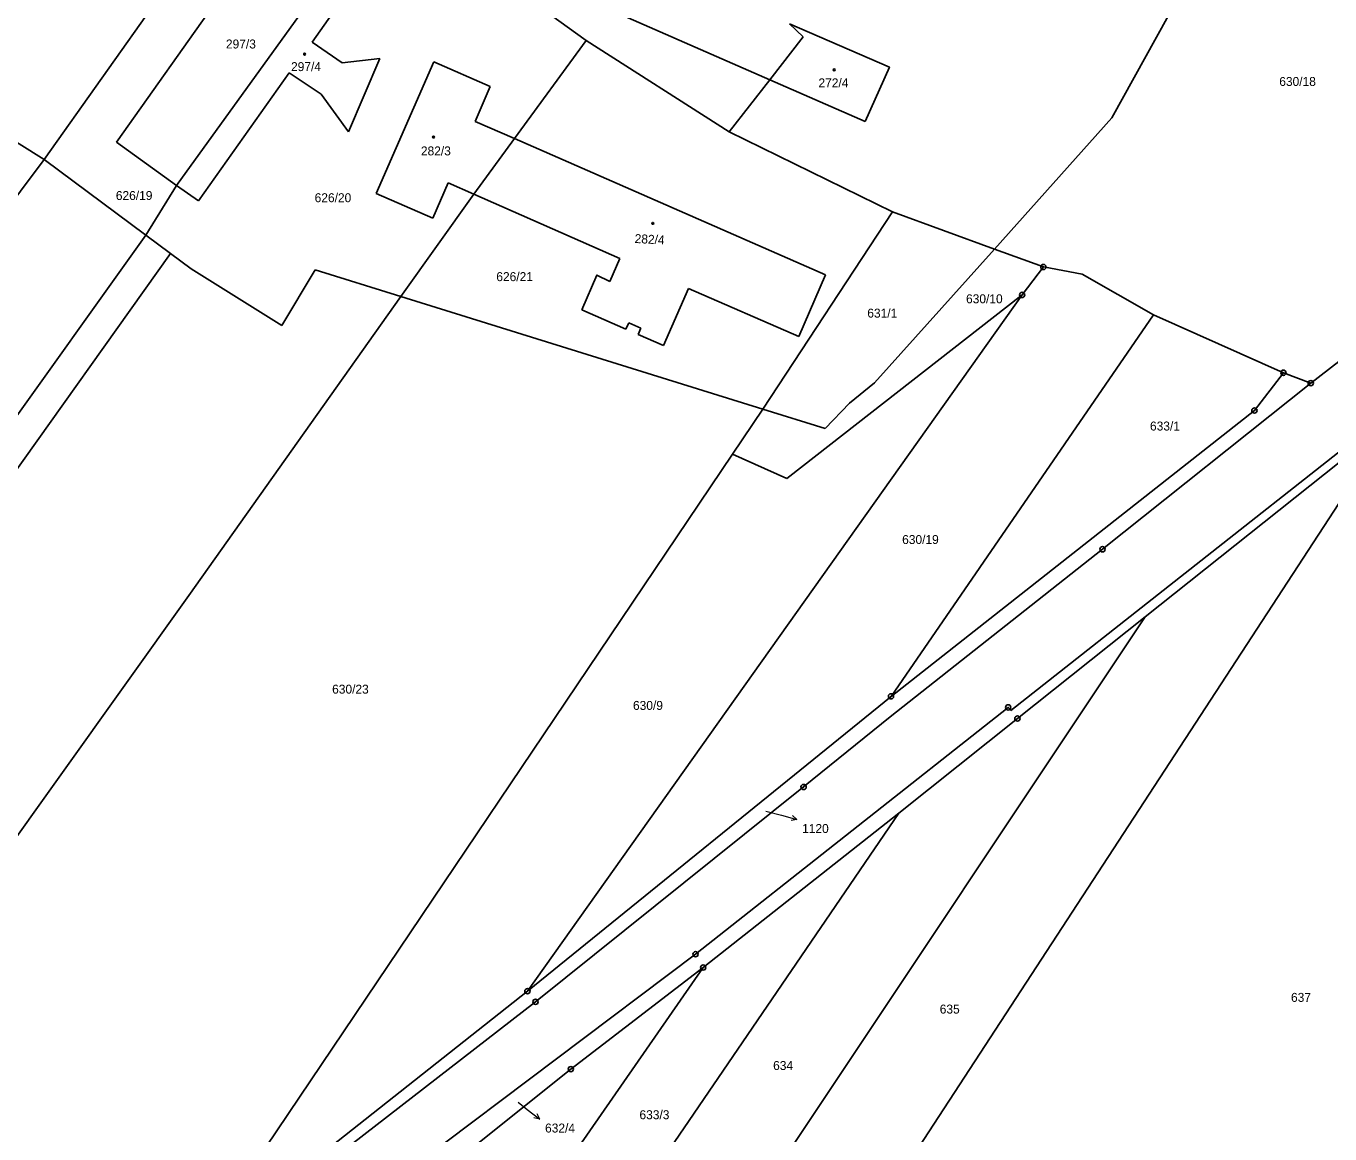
# Model space of a CAD drawing. Extents: x -694609 to -690140, y -1033292 to -1029794.
# Drawn here: x -692351.9 to -692104.2, y -1031915.8 to -1031705.3 of the extents above; entities that cross this region are included whole.
import ezdxf
from ezdxf.enums import TextEntityAlignment as Align

# ---------------------------------------------------------------- set-up
doc = ezdxf.new("R2010")
doc.units = 0
doc.header["$LTSCALE"] = 0.68
for name, color, linetype, lineweight in [('1', 7, 'Continuous', 25), ('5', 7, 'Continuous', 25), ('7', 7, 'Continuous', 13), ('8', 7, 'Continuous', 25)]:
    doc.layers.add(name, color=color, linetype=linetype, lineweight=lineweight)
doc.layers.add('2', color=7, linetype='Continuous')

msp = doc.modelspace()

# ---------------------------------------------------------------- linework, layer by layer
at = {"layer": '1'}
for p, q in [((-692334.77, -1031727.41), (-692299.54, -1031677.74)), ((-692120.78, -1031677.81), (-692145.66, -1031722.81)), ((-692245.5, -1031708.12), (-692283.59, -1031680.54)), ((-692287.71, -1031686.16), (-692323.37, -1031735.66)), ((-692283.83, -1031688.91), (-692297.6, -1031708.4)), ((-692410, -1031692.14), (-692348.49, -1031730.69)), ((-692321.31, -1031692.32), (-692348.49, -1031730.69)), ((-692210.65, -1031715.54), (-692263.5, -1031692.38)), ((-692204.33, -1031707.41), (-692206.91, -1031704.9)), ((-692204.33, -1031707.41), (-692210.65, -1031715.54)), ((-692291.9, -1031712.32), (-692297.6, -1031708.4)), ((-692245.5, -1031708.12), (-692259.11, -1031726.73)), ((-692218.38, -1031725.47), (-692245.5, -1031708.12)), ((-692284.71, -1031711.48), (-692291.9, -1031712.32)), ((-692290.69, -1031725.44), (-692284.71, -1031711.48)), ((-692285.43, -1031737.17), (-692274.48, -1031712.12)), ((-692274.48, -1031712.12), (-692263.73, -1031716.82)), ((-692301.93, -1031714.25), (-692319.15, -1031738.53)), ((-692301.93, -1031714.25), (-692295.83, -1031718.26)), ((-692263.73, -1031716.82), (-692266.63, -1031723.45)), ((-692210.65, -1031715.54), (-692218.38, -1031725.47)), ((-692192.5, -1031723.49), (-692210.65, -1031715.54)), ((-692295.83, -1031718.26), (-692290.69, -1031725.44)), ((-692038.82, -1031719.67), (-692107.88, -1031773.18)), ((-692259.11, -1031726.73), (-692266.63, -1031723.45)), ((-692145.66, -1031722.81), (-692167.96, -1031747.7)), ((-692334.77, -1031727.41), (-692323.37, -1031735.66)), ((-692259.11, -1031726.73), (-692266.83, -1031737.29)), ((-692200.03, -1031752.6), (-692259.11, -1031726.73)), ((-692218.38, -1031725.47), (-692187.33, -1031740.61)), ((-692348.49, -1031730.69), (-692363.26, -1031750.4)), ((-692348.49, -1031730.69), (-692329.14, -1031745.08)), ((-692271.76, -1031735.13), (-692274.64, -1031741.82)), ((-692266.83, -1031737.29), (-692271.76, -1031735.13)), ((-692323.37, -1031735.66), (-692329.14, -1031745.08)), ((-692323.37, -1031735.66), (-692319.15, -1031738.53)), ((-692274.64, -1031741.82), (-692285.43, -1031737.17)), ((-692266.83, -1031737.29), (-692280.75, -1031756.7)), ((-692239.1, -1031749.48), (-692266.83, -1031737.29)), ((-692187.33, -1031740.61), (-692211.93, -1031778.1)), ((-692187.33, -1031740.61), (-692167.96, -1031747.7)), ((-692366.63, -1031797.44), (-692329.14, -1031745.08)), ((-692329.14, -1031745.08), (-692324.48, -1031748.55)), ((-692428.17, -1031894.13), (-692324.48, -1031748.55)), ((-692324.48, -1031748.55), (-692320.55, -1031751.47)), ((-692241.01, -1031753.84), (-692239.1, -1031749.48)), ((-692167.96, -1031747.7), (-692190.72, -1031773.1)), ((-692158.67, -1031751.11), (-692167.96, -1031747.7)), ((-692303.33, -1031762.2), (-692320.55, -1031751.47)), ((-692296.99, -1031751.65), (-692303.33, -1031762.2)), ((-692280.75, -1031756.7), (-692296.99, -1031751.65)), ((-692158.67, -1031751.11), (-692162.71, -1031756.42)), ((-692151.29, -1031752.5), (-692158.67, -1031751.11)), ((-692137.74, -1031760.17), (-692151.29, -1031752.5)), ((-692200.03, -1031752.6), (-692205.15, -1031764.34)), ((-692280.75, -1031756.7), (-692321.02, -1031813.52)), ((-692211.93, -1031778.1), (-692280.75, -1031756.7)), ((-692162.71, -1031756.42), (-692256.68, -1031888.68)), ((-692226.07, -1031755.19), (-692230.83, -1031766.04)), ((-692205.15, -1031764.34), (-692226.07, -1031755.19)), ((-692207.41, -1031791.3), (-692162.71, -1031756.42)), ((-692237.96, -1031762.91), (-692246.32, -1031759.24)), ((-692237.44, -1031761.72), (-692237.96, -1031762.91)), ((-692235.12, -1031762.73), (-692237.44, -1031761.72)), ((-692187.61, -1031832.67), (-692137.74, -1031760.17)), ((-692113.06, -1031771.2), (-692137.74, -1031760.17)), ((-692235.65, -1031763.93), (-692235.12, -1031762.73)), ((-692230.83, -1031766.04), (-692235.65, -1031763.93)), ((-692113.06, -1031771.2), (-692118.58, -1031778.38)), ((-692107.88, -1031773.18), (-692113.06, -1031771.2)), ((-692190.72, -1031773.1), (-692195.5, -1031776.99)), ((-692147.44, -1031804.73), (-692107.88, -1031773.18)), ((-692195.5, -1031776.99), (-692200.12, -1031781.77)), ((-692090.86, -1031778.11), (-692235.26, -1031999.32)), ((-692211.93, -1031778.1), (-692217.71, -1031786.68)), ((-692200.12, -1031781.77), (-692211.93, -1031778.1)), ((-692118.58, -1031778.38), (-692187.61, -1031832.67)), ((-692164.83, -1031835.36), (-692091.71, -1031777.68)), ((-692217.71, -1031786.68), (-692314.33, -1031930.08)), ((-692207.41, -1031791.3), (-692217.71, -1031786.68)), ((-692187.79, -1031836.58), (-692147.44, -1031804.73)), ((-692321.02, -1031813.52), (-692390.46, -1031910.76)), ((-692139.32, -1031817.57), (-692253.16, -1031988.28)), ((-692139.32, -1031817.57), (-692163.6, -1031836.89)), ((-692187.61, -1031832.67), (-692256.68, -1031888.68)), ((-692224.74, -1031881.65), (-692165.36, -1031834.77)), ((-692204.22, -1031849.89), (-692187.79, -1031836.58)), ((-692165.36, -1031834.77), (-692164.83, -1031835.36)), ((-692186.12, -1031854.89), (-692163.6, -1031836.89)), ((-692255.15, -1031890.7), (-692204.22, -1031849.89)), ((-692186.12, -1031854.89), (-692269.69, -1031977.19)), ((-692223.3, -1031884.19), (-692186.12, -1031854.89)), ((-692294, -1031933.76), (-692224.74, -1031881.65)), ((-692223.3, -1031884.19), (-692282.47, -1031969.27)), ((-692248.44, -1031903.49), (-692223.3, -1031884.19)), ((-692256.68, -1031888.68), (-692300.3, -1031923.14)), ((-692310.91, -1031933.83), (-692255.15, -1031890.7)), ((-692288.84, -1031935.74), (-692248.44, -1031903.49))]:
    msp.add_line(p, q, dxfattribs=at)
for points in [[(-692206.91, -1031704.9), (-692187.92, -1031713.17), (-692192.5, -1031723.49)], [(-692246.32, -1031759.24), (-692243.47, -1031752.66), (-692241.01, -1031753.84)], [(-692139.32, -1031817.57), (-692102.45, -1031788.25), (-692090.86, -1031778.11)]]:
    msp.add_lwpolyline(points, dxfattribs=at)
at = {"layer": '5'}
for centre in [(-692299.0068, -1031710.6692), (-692198.3968, -1031713.6692), (-692274.5068, -1031726.4292), (-692232.8568, -1031742.8292)]:
    msp.add_circle(centre, 0.175, dxfattribs=at)
at = {"layer": '7'}
for p, q in [((-692205.491, -1031856.047), (-692206.329, -1031855.304)), ((-692254.335, -1031912.968), (-692254.816, -1031911.956))]:
    msp.add_line(p, q, dxfattribs=at)
for points in [[(-692211.38, -1031854.45), (-692208.39, -1031855.27), (-692205.491, -1031856.047), (-692206.588, -1031856.271)], [(-692258.46, -1031909.74), (-692256.7, -1031911.12), (-692254.335, -1031912.968), (-692255.433, -1031912.746)]]:
    msp.add_lwpolyline(points, dxfattribs=at)
at = {"layer": '8'}
for centre, radius in [((-692158.67, -1031751.1099), 0.5), ((-692158.67, -1031751.1099), 0.0303), ((-692162.71, -1031756.4199), 0.5), ((-692162.71, -1031756.4199), 0.0303), ((-692113.06, -1031771.1999), 0.5), ((-692113.06, -1031771.1999), 0.0303), ((-692107.88, -1031773.1799), 0.5), ((-692107.88, -1031773.1799), 0.0303), ((-692118.58, -1031778.3799), 0.5), ((-692118.58, -1031778.3799), 0.0303), ((-692147.44, -1031804.7299), 0.5), ((-692147.44, -1031804.7299), 0.0303), ((-692187.61, -1031832.6699), 0.5), ((-692187.61, -1031832.6699), 0.0303), ((-692165.36, -1031834.7699), 0.5), ((-692165.36, -1031834.7699), 0.0303), ((-692163.6, -1031836.8899), 0.5), ((-692163.6, -1031836.8899), 0.0303), ((-692204.22, -1031849.8899), 0.5), ((-692204.22, -1031849.8899), 0.0303), ((-692224.74, -1031881.6499), 0.5), ((-692224.74, -1031881.6499), 0.0303), ((-692223.3, -1031884.1899), 0.5), ((-692223.3, -1031884.1899), 0.0303), ((-692256.68, -1031888.6799), 0.5), ((-692256.68, -1031888.6799), 0.0303), ((-692255.15, -1031890.6999), 0.5), ((-692255.15, -1031890.6999), 0.0303), ((-692248.44, -1031903.4899), 0.5), ((-692248.44, -1031903.4899), 0.0303)]:
    msp.add_circle(centre, radius, dxfattribs=at)

# ---------------------------------------------------------------- texts
at = {"layer": '2'}
for s, p in [('297/3', (-692311.11, -1031709.605)), ('297/4', (-692298.74, -1031713.905)), ('272/4', (-692198.55, -1031716.985)), ('630/18', (-692110.38, -1031716.725)), ('282/3', (-692274.07, -1031729.915)), ('626/19', (-692331.39, -1031738.385)), ('626/20', (-692293.62, -1031738.805)), ('626/21', (-692259.11, -1031753.795)), ('630/10', (-692169.88, -1031758.005)), ('631/1', (-692189.27, -1031760.725)), ('633/1', (-692135.57, -1031782.175)), ('630/19', (-692182.02, -1031803.735)), ('630/23', (-692290.3, -1031832.155)), ('630/9', (-692233.78, -1031835.245)), ('635', (-692176.459, -1031892.925)), ('637', (-692109.729, -1031890.705)), ('634', (-692208.109, -1031903.645)), ('633/3', (-692232.55, -1031912.995))]:
    msp.add_text(s, height=1.7, dxfattribs=at).set_placement(p, align=Align.CENTER)
msp.add_text('282/4', height=1.7, rotation=357, dxfattribs=at).set_placement((-692233.5095, -1031746.6946), align=Align.CENTER)
for s, p in [('1120', (-692204.5, -1031858.625)), ('632/4', (-692253.33, -1031915.525))]:
    msp.add_text(s, height=1.7, dxfattribs=at).set_placement(p)

doc.saveas('drawing.dxf')
